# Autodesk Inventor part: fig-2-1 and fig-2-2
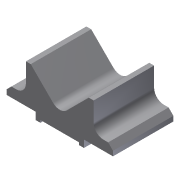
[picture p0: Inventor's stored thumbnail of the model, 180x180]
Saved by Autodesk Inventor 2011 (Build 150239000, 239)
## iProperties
Shininess: 64.0
Length Units: 11269
Angle Units: 11279
Time Units: 11290
Mass Units: 11283
Length Display Precision: 3
Angle Display Precision: 2
Compacted: True
Part Number: fig-2-1 and fig-2-2
Document SubType Name: Modeling
Created: 2002-11
Designer: deepak
Density: 1 g/cm^3
Density: 0.0
Volumn: 0.0
Area: 0.0
PropertySet Name: Model Information
Control State: 0
Master: False
Checked Out: False
Author: deepak
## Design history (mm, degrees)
sketch "Sketch1"
  geometry: L1 (0, 0)-(-3, 3); L2 (-3, 3)-(-3.5, 3); L3 (-3.5, 3)-(-3.5, 0); L4 (-3.5, 0)-(-5.5, 0); L5 (-5.5, 0)-(-5.5, -1); L6 (-5.5, -1)-(-2.5, -1); L7 (-2.5, -1)-(-2.5, -1.75); L8 (-2.5, -1.75)-(-2, -1.75); L9 (-2, -1.75)-(-2, -1.5); L10 (-2, -1.5)-(2, -1.5); L11 (2, -1.5)-(2, -1.75); L12 (2, -1.75)-(2.5, -1.75); L13 (2.5, -1.75)-(2.5, -1); L14 (2.5, -1)-(5.5, -1); L15 (5.5, -1)-(5.5, 0); L16 (5.5, 0)-(3.5, 0); L17 (3.5, 0)-(3.5, 3); L18 (3.5, 3)-(3, 3); L19 (3, 3)-(0, 0)
  constraints: 38 end point, 17 perpendicular, 1 horizontal
extrude "Extrusion1" new body sketch "Sketch1" distance "d0" = 6.25; taper "d1" = 0 deg
fillet "Fillet1" dims "d2" = 1
chamfer "Chamfer1" distance "d3" = 0.5; stored, may be unused: second distance "d4" = 2, angle "d5" = 45 deg
body "Solid1"
